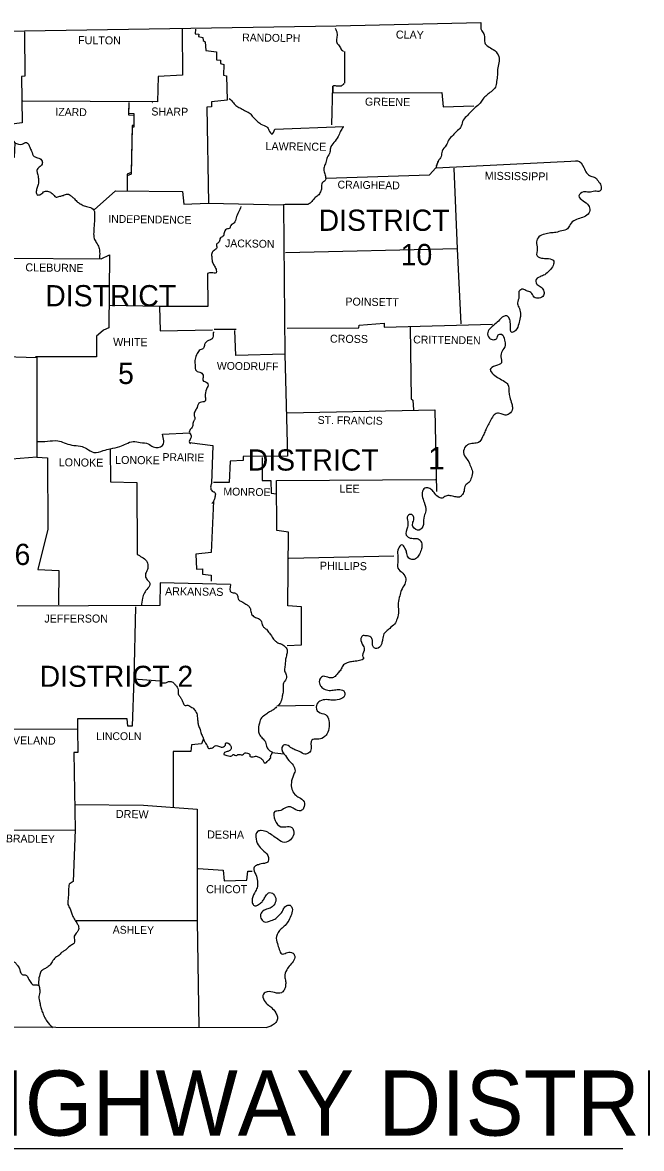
# Model space of a CAD drawing. Extents: x -17742 to 32032, y -17264 to 5867.
# Drawn here: x 3114 to 4942, y 2539 to 5867 of the extents above; entities that cross this region are included whole.
import ezdxf

# ---------------------------------------------------------------- set-up
doc = ezdxf.new("R2010")
doc.units = 0
for name, color, linetype in [('1', 7, 'Continuous'), ('2', 7, 'Continuous'), ('3', 7, 'Continuous')]:
    doc.layers.add(name, color=color, linetype=linetype)

msp = doc.modelspace()

# ---------------------------------------------------------------- linework, layer by layer
at = {"layer": '1'}
for p, q in [((4335.5, 5436.9), (4342.1, 5457.3)), ((4337.1, 5443.5), (4343.7, 5459.5)), ((3679.5, 4960.3), (3744.9, 4960.3)), ((3865.5, 3847.5), (3975.5, 3849.1)), ((1374.2, 2539.3), (4887.3, 2539.3))]:
    msp.add_line(p, q, dxfattribs=at)
for points in [[(1448.3, 5841.4), (2338.2, 5840.9), (3119.2, 5842.5), (4040.5, 5856.8), (4467.6, 5866.7)], [(3119.2, 5839.2), (3120.3, 5708.2), (3110.9, 5707.7), (3112.6, 5570.7), (3074.1, 5565.2), (3077.4, 5528.3), (3090.6, 5511.2), (3089.5, 5467.7), (3014.6, 5465), (3011.9, 5397.8), (2943.6, 5395.6), (2940.3, 5314.2), (2944.2, 5307.6), (2945.8, 5177.7), (3063.6, 5170), (3062, 4880), (3155.5, 4877.2), (3155.5, 4582.2), (3081.8, 4576.7), (3076.3, 4511.8), (2952.4, 4511.2)], [(3585.3, 5847.5), (3586.4, 5711), (3514.9, 5707.1), (3512.7, 5632.3), (3114.8, 5634.5)], [(3625, 5846.9), (3623.3, 5833.7), (3634.3, 5832.1), (3633.8, 5825.5), (3646.4, 5822.7), (3647.5, 5813.9), (3653.6, 5810.1), (3655.2, 5783.6), (3686.6, 5780.3), (3686.6, 5756.7), (3698.2, 5755), (3698.2, 5745.7), (3708.1, 5742.9), (3707.5, 5711), (3716.3, 5709.3), (3718.5, 5637.2), (3671.7, 5632.8), (3672.3, 5617.4), (3658, 5616.9), (3662.9, 5332.9), (3884.7, 5327.9), (3888.6, 4886.6), (3743.8, 4882.7), (3741.1, 4957)], [(4064.7, 5780.9), (4064.7, 5687.9)], [(4027.3, 5564.1), (4030, 5679.1), (4030, 5658.7), (4352, 5660.4), (4356.4, 5617.4), (4447.2, 5620.7)], [(3427.9, 5630.6), (3426.8, 5598.7), (3442.3, 5597.6), (3442.8, 5562.4), (3437.3, 5562.4), (3435.1, 5423.7), (3422.4, 5418.2), (3422.4, 5372)], [(3427.9, 5625.7), (3426.8, 5593.8), (3442.3, 5592.7), (3442.8, 5557.4), (3437.3, 5557.4), (3435.1, 5418.8), (3422.4, 5413.3), (3422.4, 5367)], [(3496.7, 5629.5), (3497.3, 5630.1)], [(3858.9, 5551.9), (4063.1, 5559.1)], [(4335.5, 5436.9), (4753.2, 5458.4)], [(4010.8, 5406.7), (4316.2, 5416.6), (4334.4, 5437.5)], [(4388.3, 5436.4), (4397.7, 5198.1), (4408.7, 4976.3)], [(3325.6, 5313.1), (3388.3, 5369.8), (3586.4, 5367), (3590.3, 5330.2), (3662.4, 5332.9)], [(3956.8, 5329.1), (3889.7, 5329.1), (3884.7, 5327.9)], [(4397.7, 5198.1), (3890.8, 5186.5)], [(3063.6, 5170), (3346.5, 5168.3), (3370.7, 5179.9), (3369.1, 4964.7), (3352.5, 4957.6), (3337.7, 4944.9), (3332.7, 4940), (3332.2, 4878.3), (3152.2, 4878.3)], [(3660.2, 5124.9), (3661.3, 5028), (3518.2, 5027.5), (3371.3, 5030.2)], [(3518.2, 5027.5), (3520.4, 4955.4), (3675.1, 4958.1)], [(3895.2, 4963.6), (4107.6, 4964.7), (4108.2, 4972.4), (4181.9, 4977.9), (4181.9, 4966.4), (4502.2, 4975.2)], [(4259, 4966.4), (4261.7, 4754.5), (4266.7, 4751.2), (4268.3, 4722.6)], [(3679.5, 4951), (3676.7, 4950.4)], [(3888.6, 4886.6), (3896.8, 4585), (3765.9, 4584.4), (3765.3, 4572.3), (3727.3, 4570.1), (3724, 4507.4), (3677.8, 4507.4)], [(3895.2, 4713.2), (4332.2, 4722)], [(4332.2, 4722), (4336.6, 4481)], [(3527, 4650.5), (3606.8, 4654.3)], [(3606.8, 4625.7), (3675.6, 4616.9), (3671.7, 4504.6)], [(3372.9, 4607.5), (3374, 4509), (3451.6, 4507.4), (3452.2, 4296)], [(3155.5, 4582.2), (3187.4, 4580), (3188, 4369.8), (3159.4, 4250.4), (3220.5, 4247.6), (3219.9, 4146.3)], [(3822, 4581.7), (3821.4, 4513.4), (3846.8, 4513.4), (3847.9, 4475.5), (3863.8, 4473.8)], [(3895.2, 4025.3), (3938.1, 4028), (3937.6, 4139.7), (3897.4, 4142.5), (3899.6, 4361), (3864.9, 4365.9), (3863.8, 4512.9), (4333.3, 4516.2)], [(3677.8, 4451.8), (3671.2, 4301), (3626.1, 4296), (3627.2, 4251.5), (3645.3, 4252), (3645.9, 4236.6), (3670.6, 4233.8), (3671.2, 4215.7)], [(3900.7, 4283.4), (4211.1, 4291.1)], [(3728.4, 4205.8), (3520.4, 4211.3), (3519.3, 4143.6), (3098.3, 4141.9)], [(3447.2, 4140.3), (3442.8, 3927.3), (3519.3, 3921.2)], [(3442.8, 3927.3), (3437.8, 3787.5), (3425.2, 3787.5), (3423, 3809), (3276.6, 3809), (3276.6, 3778.2)], [(3080.7, 3779.8), (3275.5, 3778.7)], [(3276.6, 3778.7), (3277.1, 3709.9), (3265.6, 3709.4), (3268.9, 3481)], [(3648.6, 3749.5), (3642, 3734.7), (3612.9, 3731.9), (3611.2, 3712.1), (3558.9, 3712.1), (3558.4, 3547.6)], [(3267.2, 3555.8), (3471.4, 3554.2), (3629.9, 3542.1)], [(3629.9, 3542.1), (3629.9, 3212.9), (3634.3, 2896.5)], [(3020.1, 3480.4), (3268.9, 3481)], [(3268.9, 3481), (3263.4, 3328), (3251.3, 3320.3)], [(3632.7, 3366.5), (3706.4, 3362.1), (3709.7, 3330.2), (3776.3, 3332.4), (3779.1, 3359.3), (3791.7, 3359.3)], [(3272.2, 3213.5), (3629.9, 3213.5)], [(1964.6, 2899.5), (3835.2, 2896.5)]]:
    msp.add_lwpolyline(points, dxfattribs=at)
for points in [[(4467.6, 5866.7), (4470.3, 5842.5), (4478, 5829.9), (4479.1, 5806.8), (4488.5, 5796.9), (4504.4, 5786.9), (4518.7, 5771), (4522, 5752.3), (4517.6, 5733), (4516.5, 5711.5), (4514.3, 5692.8), (4511, 5675.8), (4497.8, 5662), (4485.2, 5652.1), (4473.6, 5640.6), (4465.4, 5628.4), (4451.1, 5615.2), (4436.7, 5601.5), (4425.2, 5589.4), (4413.6, 5574), (4408.1, 5556.9), (4395.5, 5544.8), (4385.6, 5533.8), (4372.4, 5518.9), (4365.7, 5504.1), (4353.1, 5487), (4350.3, 5470.5), (4342.1, 5457.3), (4341.5, 5455.1)], [(4037.7, 5849.7), (4042.7, 5835.9), (4042.1, 5821.1), (4042.1, 5807.3), (4049.3, 5798), (4056.4, 5786.4), (4062, 5781.4)], [(4062.5, 5686.2), (4055.3, 5679.1), (4041.6, 5679.1), (4030, 5679.1)], [(3724.6, 5642.2), (3736.7, 5629.5), (3747.1, 5619.1), (3759.3, 5613), (3773.6, 5604.8), (3786.2, 5598.2), (3794.5, 5587.7), (3806, 5576.2), (3817.6, 5566.8), (3835.8, 5558), (3841.8, 5548.6), (3850.1, 5537.1), (3858.9, 5551.9)], [(4061.4, 5558.5), (4053.1, 5545.3), (4046.5, 5529.9), (4033.3, 5512.3), (4023.4, 5495.3), (4021.8, 5483.7), (4014.1, 5468.3), (4009.7, 5452.9), (4004.7, 5439.7), (4004.7, 5425.9), (4008.6, 5412.2), (4007.5, 5399.5), (3999.2, 5393.4), (3997, 5377.5), (3993.7, 5366.5), (3986.6, 5355.5), (3976.1, 5347.2), (3965.1, 5334.6), (3956.8, 5329.1)], [(3090.6, 5511.2), (3112.6, 5507.4), (3125.8, 5512.3), (3135.2, 5498), (3140.1, 5487), (3148.4, 5471), (3161.6, 5466.1), (3171.5, 5457.3), (3171.5, 5447.9), (3162.7, 5439.1), (3156.1, 5430.3), (3158.3, 5419.9), (3160.5, 5405.5), (3160.5, 5391.8), (3157.2, 5379.1), (3154.4, 5367.6), (3157.2, 5357.7), (3167.6, 5359.3), (3178.6, 5367.6), (3190.2, 5367.6), (3201.2, 5361.5), (3212.8, 5351.1), (3224.3, 5353.3), (3233.7, 5356), (3246.9, 5359.9), (3256.2, 5354.9), (3264.5, 5348.3), (3274.4, 5337.9), (3283.8, 5331.3), (3295.9, 5325.2), (3310.7, 5321.3), (3324.5, 5312), (3326.7, 5296), (3326.1, 5282.3), (3325, 5265.2), (3323.9, 5246.5), (3325.6, 5228.3), (3331.6, 5216.2), (3339.3, 5201.9), (3341.5, 5188.7), (3341, 5167.8)], [(4747.1, 5457.8), (4753.2, 5458.4), (4771.9, 5438.6), (4780.2, 5422.1), (4792.3, 5412.7), (4806, 5407.8), (4816.5, 5395.1), (4823.6, 5381.3), (4819.8, 5369.2), (4804.4, 5368.1), (4787.3, 5365.4), (4770.8, 5365.9), (4757.6, 5354.9), (4769.7, 5340.1), (4785.7, 5326.3), (4790.1, 5311.4), (4781.3, 5297.1), (4763.7, 5289.4), (4746.6, 5282.8), (4731.2, 5269.6), (4724, 5257), (4707, 5251.5), (4689.4, 5246.5), (4673.9, 5244.8), (4656.3, 5241.5), (4639.3, 5233.3), (4632.1, 5219), (4634.3, 5198.6), (4633.8, 5177.2), (4651.9, 5170), (4667.9, 5169.4), (4683.3, 5161.2), (4681.6, 5149.1), (4670.1, 5133.7), (4656.3, 5121.6), (4642.6, 5115.5), (4629.9, 5104), (4634.3, 5092.4), (4645.9, 5084.7), (4654.1, 5072), (4653, 5060.5), (4639.8, 5052.2), (4625.5, 5055.5), (4615.1, 5069.3), (4602.9, 5073.7), (4592.5, 5078.6), (4580.4, 5071.5), (4580.4, 5055.5), (4576, 5038.5), (4579.8, 5025.8), (4584.8, 5008.2), (4584.2, 4995), (4579.8, 4976.3), (4570.5, 4957), (4559.5, 4951), (4555.1, 4971.9), (4552.9, 4988.9), (4546.3, 4998.8), (4537.5, 4999.4), (4525.9, 4991.1), (4513.2, 4978.5), (4497.3, 4964.7), (4487.9, 4951), (4492.9, 4933.9), (4505, 4929.5), (4514.3, 4932.8), (4519.3, 4943.8), (4528.7, 4945.5), (4537.5, 4928.4)], [(3758.7, 5323), (3752.1, 5305.9), (3744.4, 5289.4), (3739.4, 5275.1), (3729, 5266.9), (3725.7, 5259.2), (3716.3, 5255.9), (3709.2, 5244.8), (3705.9, 5234.9), (3698.2, 5230.5), (3694.3, 5218.4), (3687.2, 5211.8), (3687.7, 5200.8), (3679.5, 5193.1), (3672.9, 5184.3), (3672.9, 5172.2), (3675.6, 5156.2), (3681.1, 5146.9), (3686.1, 5134.8), (3685.5, 5127.1), (3671.7, 5127.1), (3660.2, 5124.9)], [(3676.7, 4950.4), (3674, 4932.2), (3663.5, 4927.3), (3651.4, 4915.2), (3648.6, 4904.2), (3638.7, 4899.8), (3629.4, 4888.2), (3623.3, 4872.3), (3623.3, 4855.7), (3627.2, 4837), (3640.9, 4832.1), (3647.5, 4821.1), (3646.4, 4809.5), (3659.6, 4801.8), (3661.8, 4795.2), (3659.6, 4788.1), (3653.6, 4767.7), (3654.1, 4753.9), (3653, 4747.9), (3638.2, 4744), (3629.4, 4729.2), (3623.3, 4718.7), (3621.1, 4704.9), (3622.8, 4695), (3618.4, 4687.3), (3616.7, 4675.8), (3611.2, 4665.9), (3606.3, 4656.5), (3611.8, 4645.5), (3610.1, 4637.8), (3606.8, 4625.7), (3609.6, 4621.8)], [(4537.5, 4928.4), (4539.7, 4912.4), (4530.3, 4895.4), (4527, 4878.3), (4528.7, 4861.2), (4511, 4851.9), (4495.6, 4840.9), (4504.4, 4827.7), (4520.9, 4815.6), (4537.5, 4806.2), (4547.9, 4796.9), (4550.7, 4774.3), (4553.4, 4760), (4558.9, 4740.2), (4561.1, 4726.4), (4551.2, 4709.9), (4539.7, 4706.6), (4527.5, 4710.5), (4513.2, 4711.6), (4501.7, 4700.5), (4493.4, 4685.1), (4485.2, 4669.7), (4479.1, 4656.5), (4473.1, 4642.2), (4461, 4625.7), (4446.1, 4622.9), (4428.5, 4618.5), (4418, 4606.4), (4419.7, 4586.1), (4429.6, 4572.3), (4437.3, 4555.3), (4442.8, 4540.4), (4440, 4521.7), (4432.3, 4507.9), (4422.4, 4499.7), (4418, 4482.1), (4410.9, 4468.8), (4404.3, 4464.4), (4391.1, 4465.5), (4376.8, 4468.3), (4364.6, 4467.2), (4353.1, 4461.1), (4341.5, 4465), (4329.4, 4478.2), (4319.5, 4488.1), (4308.5, 4492), (4297, 4485.9), (4294.8, 4467.7), (4300.3, 4449), (4305.2, 4423.7), (4300.3, 4408.3), (4298.6, 4383)], [(3156.6, 4628.5), (3187.4, 4629.6), (3217.7, 4630.7), (3237, 4625.1), (3259, 4618), (3284.9, 4614.7), (3303, 4607.5), (3324.5, 4596.5), (3352, 4601.5), (3373.5, 4607), (3401.5, 4614.1), (3419.7, 4621.8), (3440.6, 4628.5), (3461.5, 4625.7), (3485.2, 4621.3), (3500, 4612.5), (3527, 4616.3), (3527, 4650.5)], [(3671.7, 4504.6), (3669.5, 4493.6), (3674, 4482.1), (3681.7, 4478.2), (3682.8, 4467.2), (3680, 4456.2), (3677.8, 4451.8), (3672.9, 4445.2)], [(4298.6, 4383), (4285.9, 4367), (4267.2, 4376.9), (4267.2, 4390.1), (4270, 4403.9), (4263.4, 4412.7), (4251.8, 4408.9), (4251.8, 4391.8), (4250.7, 4375.3), (4247.4, 4351.6), (4255.1, 4344.5), (4272.7, 4342.3), (4285.4, 4339), (4293.1, 4326.3), (4292.5, 4310.9), (4286.5, 4296), (4277.7, 4283.9), (4263.9, 4279.5), (4252.9, 4286.7), (4248.5, 4301), (4243.6, 4313.6), (4234.2, 4323), (4224.3, 4312.5), (4222.1, 4293.3), (4222.7, 4276.8), (4222.7, 4254.2), (4237, 4239.3), (4245.8, 4222.3), (4243, 4206.9), (4232.6, 4188.7), (4228.2, 4172.8), (4223.8, 4151.3), (4224.3, 4127.6), (4220.5, 4104.5), (4212.7, 4089.1), (4198.4, 4076.4), (4189.1, 4068.2), (4181.4, 4059.9), (4177.5, 4043.4), (4174.8, 4031.9), (4164.3, 4018.1), (4156.1, 4017), (4149.5, 4022.5), (4147.3, 4031.9), (4147.3, 4041.2), (4142.9, 4050.6), (4129.1, 4054.4), (4118.1, 4053.9), (4113.1, 4046.2), (4120.3, 4024.7), (4123, 4011), (4119.2, 3992.2), (4121.4, 3990), (4101.6, 3979.6), (4085.6, 3977.9), (4072.4, 3974.1), (4059.7, 3965.8), (4053.7, 3953.7), (4044.9, 3943.8), (4037.2, 3934.5), (4026.7, 3930.1), (4015.2, 3932.3), (3999.8, 3933.9), (3991, 3922.9), (3993.7, 3906.9), (4004.2, 3897.6), (4019.6, 3893.2), (4035.5, 3894.3), (4050.9, 3895.9), (4065.3, 3888.2), (4062.5, 3873.4), (4048.7, 3866.2), (4028.4, 3864), (4011.9, 3865.7), (3992.1, 3861.3), (3982.1, 3848.6), (3987.7, 3829.3), (4009.1, 3821.6), (4019, 3803.5), (4019.6, 3786.4), (4012.4, 3763.8), (4002.5, 3753.4), (3983.3, 3749), (3968.4, 3746.2), (3966.2, 3720.9), (3959.6, 3708.3), (3948, 3704.4), (3931.5, 3712.7), (3921.6, 3716.5), (3909.5, 3722), (3894.1, 3731.4), (3882.5, 3729.7), (3885.8, 3705.5), (3886.9, 3704.4), (3900.1, 3686.2), (3913.4, 3671.9), (3919.4, 3654.9)], [(3452.2, 4296), (3465.9, 4286.7), (3480.2, 4275.7), (3484.1, 4260.8), (3483, 4250.4), (3478.6, 4241.6), (3477.5, 4227.8), (3484.1, 4217.9), (3490.1, 4209.6), (3484.1, 4194.8), (3473.6, 4181), (3468.1, 4165.6), (3464.3, 4142.5)], [(3728.4, 4205.8), (3730.1, 4183.2), (3743.3, 4179.9), (3748.8, 4173.9), (3751.6, 4161.2), (3760.9, 4155.7), (3773.6, 4148), (3781.3, 4142.5), (3786.8, 4133.7), (3790.1, 4119.4), (3798.9, 4110), (3811, 4105.6), (3819.8, 4095.2), (3825.3, 4080.3), (3834.1, 4073.7), (3842.9, 4062.1), (3847.3, 4057.2), (3855, 4044), (3862.7, 4037.4), (3868.2, 4033.5), (3877, 4030.8), (3888, 4023.6), (3895.2, 4012.6), (3895.2, 4004.3), (3892.4, 3991.7), (3890.2, 3978.5), (3889.1, 3963.6), (3888, 3950.4), (3893, 3939.4), (3890.2, 3922.9), (3884.7, 3914.1), (3884.2, 3902), (3882.5, 3883.8), (3880.3, 3873.4), (3875.4, 3856.3), (3868.2, 3847.5)], [(3519.3, 3921.2), (3527.6, 3915.7), (3539.1, 3916.3), (3546.8, 3919.6), (3552.9, 3919), (3561.1, 3914.1), (3566.6, 3907.5), (3570.5, 3902.5), (3573.2, 3894.8), (3573.2, 3887.7), (3576, 3877.8), (3579.3, 3873.9), (3583.7, 3866.8), (3586.4, 3860.2), (3588.1, 3855.8), (3594.1, 3848.6), (3599.7, 3849.1), (3604.6, 3848.6), (3611.2, 3844.7), (3621.1, 3837), (3622.8, 3834.8), (3629.4, 3820.5), (3630.5, 3811.7), (3631.6, 3800.2), (3633.8, 3789.2), (3638.2, 3777.1), (3640.4, 3768.8), (3645.3, 3757.2), (3648.6, 3749.5), (3653, 3739.6), (3659.6, 3728.6), (3662.4, 3722), (3671.7, 3722.6), (3678.4, 3725.3), (3683.3, 3729.7), (3689.4, 3729.2), (3696, 3727), (3704.8, 3725.3), (3710.3, 3728.6), (3713, 3730.8), (3713.6, 3735.8), (3718.5, 3738.5), (3724, 3734.7), (3730.1, 3725.9), (3730.1, 3720.4), (3727.9, 3717.1), (3720.7, 3712.7), (3710.8, 3709.4), (3708.1, 3705.5), (3717.4, 3701.1), (3732.3, 3700), (3736.1, 3703.3), (3746, 3700.6), (3749.9, 3703.3), (3763.1, 3702.8), (3769.2, 3707.2), (3781.3, 3706.6), (3785.1, 3703.9), (3785.1, 3698.9), (3795, 3696.7), (3802.2, 3698.4), (3811.5, 3695.6), (3819.8, 3691.2), (3824.2, 3685.1), (3829.7, 3678.5), (3834.7, 3680.2), (3838.5, 3685.1), (3846.8, 3693.9), (3846.8, 3699.5), (3849, 3703.3), (3851.7, 3708.8)], [(3864.4, 3844.2), (3852.8, 3834.8), (3842.9, 3829.3), (3832.5, 3821.6), (3819.8, 3812.3), (3813.7, 3796.3), (3810.4, 3774.3), (3814.8, 3761.1), (3824.7, 3749.5), (3831.4, 3740.2), (3836.3, 3723.7), (3848.4, 3712.1), (3852.3, 3710.5)], [(3919.4, 3654.9), (3913.9, 3642.2), (3907.9, 3620.2), (3909.5, 3601.5), (3917.8, 3585.5), (3931, 3576.7), (3945.3, 3564.1), (3944.2, 3544.8), (3935.9, 3537.6), (3916.7, 3542.6), (3901.8, 3549.2), (3889.1, 3545.4), (3872.1, 3537.1), (3859.4, 3535.4), (3860, 3509), (3877, 3490.3), (3891.9, 3490.3), (3909, 3488.1), (3915, 3468.3), (3905.1, 3451.8), (3888.6, 3443.5), (3867.7, 3453.4), (3852.8, 3463.9), (3838, 3473.8), (3819.2, 3478.8), (3808.8, 3476.6), (3803.8, 3453.4), (3812.6, 3432.5), (3826.9, 3418.2), (3840.2, 3399.5), (3838, 3385.8), (3828.1, 3381.9), (3810.4, 3378), (3800, 3372.5), (3797.2, 3368.1), (3802.7, 3349.4), (3807.7, 3329.1), (3807.7, 3313.7), (3801.6, 3299.3), (3792.3, 3277.3), (3793.4, 3263), (3800, 3256.4), (3808.2, 3258.6), (3819.2, 3266.3), (3826.4, 3275.1), (3832.5, 3286.1), (3844, 3295.5), (3858.3, 3287.2), (3861.6, 3270.2), (3853.4, 3255.3), (3841.8, 3248.7), (3827.5, 3243.2), (3817, 3231.1), (3819.8, 3216.8), (3828.1, 3209.1), (3848.4, 3212.9), (3862.2, 3219), (3869.9, 3226.7), (3879.2, 3236.1), (3884.2, 3245.4), (3891.3, 3255.3), (3904, 3258.1), (3910.1, 3249.8), (3907.9, 3231.1), (3900.1, 3213.5), (3889.7, 3198.6), (3878.1, 3188.2), (3863.8, 3165.6), (3866.6, 3144.7), (3872.1, 3127.6), (3879.8, 3114.4), (3893, 3117.2), (3907.9, 3118.8), (3916.7, 3111.7), (3915.6, 3096.3), (3904.5, 3081.4), (3894.1, 3067.1), (3888.6, 3047.3), (3890.8, 3033.5), (3890.8, 3020.9), (3886.4, 3007.1), (3878.7, 2999.4), (3858.3, 3000), (3836.9, 3002.2), (3825.3, 2995.6), (3827.5, 2976.8), (3840.2, 2963.1), (3849, 2955.9), (3861.6, 2940.5), (3867.1, 2927.9), (3865.5, 2916.8), (3857.8, 2907.5), (3835.2, 2896.5)], [(3251.3, 3320.3), (3249.6, 3303.2), (3249.1, 3287.2), (3248, 3271.8), (3248, 3260.3), (3254.6, 3247.6), (3258.4, 3235.5), (3262.3, 3225), (3270, 3211.3), (3277.1, 3200.8), (3279.3, 3186), (3274.9, 3178.3), (3266.7, 3166.7), (3266.1, 3145.8), (3256.2, 3139.2), (3243.6, 3128.2), (3236.4, 3123.2), (3228.7, 3118.3), (3220.5, 3109.5), (3208.4, 3101.2), (3199.5, 3087.5), (3189.6, 3077), (3181.4, 3071.5), (3169.8, 3064.3), (3164.9, 3053.3), (3161, 3033), (3162.7, 3018.1), (3164.9, 3004.9), (3162.1, 2988.4), (3164.9, 2970.2), (3167.6, 2955.9), (3172, 2943.3), (3178.1, 2929), (3185.8, 2915.7), (3202.3, 2895.4)], [(2702.6, 3193.1), (2711.4, 3199.2), (2719.6, 3202.5), (2727.9, 3200.8), (2736.7, 3199.7), (2744.4, 3200.8), (2754.3, 3199.2), (2762.6, 3194.2), (2771.9, 3190.4), (2781.3, 3190.4), (2789.5, 3190.4), (2796.7, 3185.4), (2809.9, 3186), (2820.9, 3190.4), (2831.9, 3193.7), (2846.8, 3195.3), (2860, 3186), (2869.3, 3178.3), (2877, 3169.5), (2882.5, 3159.6), (2888.6, 3154.1), (2898.5, 3150.2), (2906.2, 3148.5), (2915.6, 3145.8), (2920.5, 3143.6), (2924.9, 3133.1), (2932.1, 3118.8), (2945.8, 3113.9), (2962.9, 3120.5), (2976.7, 3124.3), (2986.6, 3127.6), (2992.6, 3129.8), (2998.1, 3130.4), (2996.5, 3131.5), (3003.1, 3133.1), (3009.1, 3128.7), (3013, 3122.7), (3019.6, 3113.9), (3025.6, 3106.2), (3031.7, 3103.4), (3037.7, 3106.7), (3046, 3104), (3053.2, 3101.2), (3061.4, 3099), (3068.6, 3098.5), (3077.9, 3096.3), (3085.1, 3092.4), (3091.7, 3088.6), (3098.3, 3081.4), (3104.9, 3070.4), (3107.1, 3061.6), (3114.8, 3052.8), (3121.9, 3052.8), (3132.4, 3038.5), (3136.3, 3033), (3144.5, 3023.1), (3150.6, 3023.1), (3162.1, 3020.9)]]:
    msp.add_spline(points, degree=3, dxfattribs=at)
at = {"layer": '3'}
msp.add_line((3850.6, 3709.9), (3885.3, 3705.5), dxfattribs=at)

# ---------------------------------------------------------------- texts
at = {"layer": '1'}
msp.add_text('1', height=66, dxfattribs=at).set_placement((4311.8, 4546.4))
at = {"layer": '2'}
for s, height, rotation, p in [('FULTON', 23.66, 359.4996, (3277.7, 5802.9)), ('RANDOLPH', 23.11, 359.2583, (3762.6, 5811.2)), ('CLAY', 23.66, 359.2258, (4216.6, 5819.4)), ('GREENE', 23.67, 359.2361, (4125.2, 5621.3)), ('IZARD', 23.11, 358.9258, (3210.6, 5591.6)), ('SHARP', 23.66, 359.3905, (3494, 5592.1)), ('LAWRENCE', 23.67, 359.2678, (3831.4, 5489.8)), ('MISSISSIPPI', 23.66, 359.3097, (4479.1, 5402.2)), ('CRAIGHEAD', 23.11, 359.1159, (4044.3, 5376.4)), ('INDEPENDENCE', 23.108, 359.2187, (3366.9, 5275.1)), ('JACKSON', 23.11, 359.1352, (3711.9, 5203)), ('CLEBURNE', 23.66, 359.2535, (3121.9, 5131.5)), ('POINSETT', 23.66, 359.1987, (4067.3, 5030.4)), ('WHITE', 23.67, 359.3139, (3381.2, 4911.3)), ('CROSS', 23.66, 359.3839, (4021.8, 4920.7)), ('CRITTENDEN', 23.11, 359.213, (4267.8, 4918.5)), ('WOODRUFF', 23.11, 359.2748, (3687.7, 4840.9)), ('ST. FRANCIS', 23.108, 359.2216, (3985.5, 4680.7)), ('PRAIRIE', 23.11, 359.2116, (3527, 4571.2)), ('LONOKE', 23.67, 359.4974, (3220.5, 4555.3)), ('LONOKE', 23.67, 359.4974, (3387.2, 4562.4)), ('MONROE', 23.11, 359.0331, (3707, 4469.4)), ('LEE', 23.67, 359.4327, (4049.8, 4477.7)), ('PHILLIPS', 23.66, 359.3179, (3992.1, 4249.8)), ('ARKANSAS', 23.66, 359.2678, (3534.7, 4174.4)), ('CLEVELAND', 23.67, 359.3377, (3023.4, 3734.7)), ('DREW', 23.66, 359.2258, (3389.4, 3516.2)), ('BRADLEY', 23.11, 359.1449, (3064.7, 3444.1)), ('DESHA', 23.66, 359.3704, (3659.1, 3455.6)), ('ASHLEY', 23.11, 359.2361, (3380.1, 3174.4))]:
    msp.add_text(s, height=height, rotation=rotation, dxfattribs=at).set_placement(p)
for s, height, p in [('JEFFERSON', 23.67, (3178.1, 4093.5)), ('LINCOLN', 23.11, (3331.1, 3746.2)), ('CHICOT', 23.67, (3656.3, 3293.8)), ('ARKANSAS HIGHWAY DISTRICT 3', 192.623, (1388.2, 2577.3))]:
    msp.add_text(s, height=height, dxfattribs=at).set_placement(p)
at = {"layer": '3'}
for s, height, p in [('DISTRICT', 62.74, (3988.5, 5251.1)), ('10', 62.74, (4231, 5149.6)), ('DISTRICT', 62.74, (3180.8, 5028)), ('5', 62.7, (3396, 4798.5)), ('DISTRICT', 62.74, (3779.1, 4542.6)), ('DISTRICT 6', 62.74, (2680, 4263.6)), ('DISTRICT 2', 62.19, (3164.9, 3903.6))]:
    msp.add_text(s, height=height, dxfattribs=at).set_placement(p)

doc.saveas('drawing.dxf')
